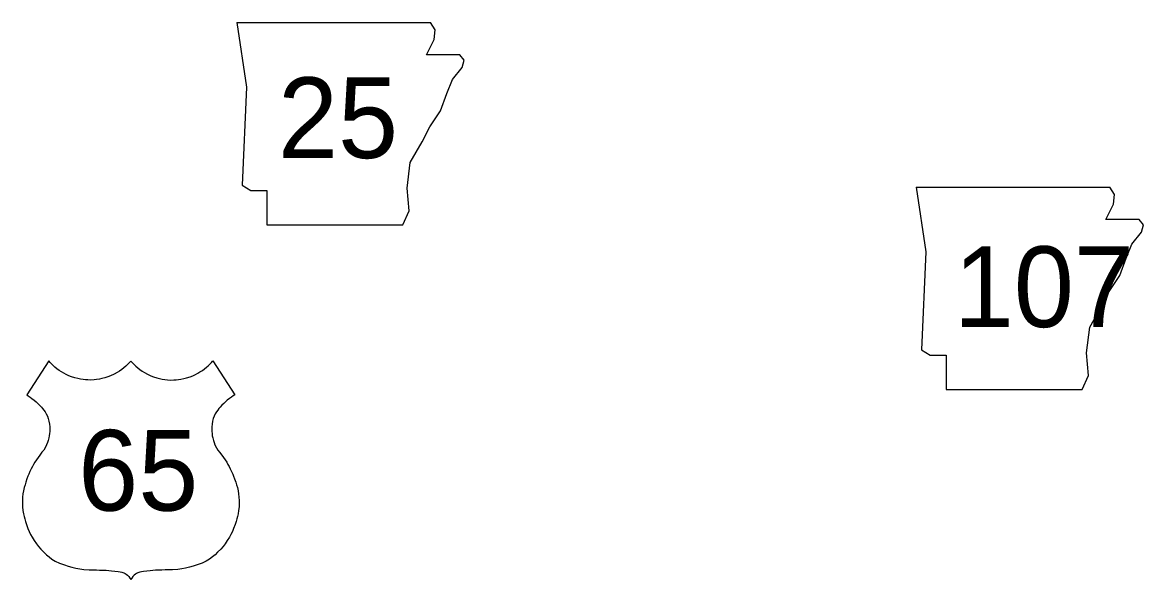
# Model space of a CAD drawing. Extents: x -819161 to 80911, y -6604 to 768454.
# Drawn here: x 43970 to 44849, y -2416 to -1978 of the extents above; entities that cross this region are included whole.
import ezdxf

# ---------------------------------------------------------------- set-up
doc = ezdxf.new("R2010")
doc.units = 0
doc.layers.add('Level 21', color=7, linetype='Continuous')
doc.layers.add('Level 22', color=7, linetype='Continuous')

msp = doc.modelspace()

# ---------------------------------------------------------------- linework, layer by layer
at = {"layer": 'Level 21'}
for p, q in [((44137.85, -1978.23), (44145.46, -2028.99)), ((44293.5, -1984.15), (44289.99, -1978.31)), ((44292.65, -1991.77), (44293.5, -1984.15)), ((44286.73, -2003.61), (44292.65, -1991.77)), ((44312.95, -2003.61), (44286.73, -2003.61)), ((44316.34, -2007.84), (44312.95, -2003.61)), ((44307.03, -2023.07), (44314.64, -2013.76)), ((44314.64, -2013.76), (44316.34, -2007.84)), ((44145.46, -2028.99), (44142.08, -2105.96)), ((44302.8, -2034.06), (44307.03, -2023.07)), ((44297.73, -2047.6), (44302.8, -2034.06)), ((44289.27, -2060.29), (44297.73, -2047.6)), ((44283.35, -2072.13), (44289.27, -2060.29)), ((44274.04, -2088.2), (44283.35, -2072.13)), ((44271.5, -2108.5), (44274.04, -2088.2)), ((44142.08, -2105.96), (44148.85, -2110.19)), ((44148.85, -2110.19), (44161.54, -2110.19)), ((44161.54, -2110.19), (44161.54, -2137.26)), ((44273.19, -2126.27), (44271.5, -2108.5)), ((44670.8, -2107.53), (44678.41, -2158.29)), ((44826.44, -2113.46), (44822.93, -2107.61)), ((44825.6, -2121.07), (44826.44, -2113.46)), ((44268.12, -2137.26), (44273.19, -2126.27)), ((44819.68, -2132.91), (44825.6, -2121.07)), ((44161.54, -2137.26), (44268.12, -2137.26)), ((44845.9, -2132.91), (44819.68, -2132.91)), ((44849.28, -2137.14), (44845.9, -2132.91)), ((44847.59, -2143.06), (44849.28, -2137.14)), ((44839.98, -2152.37), (44847.59, -2143.06)), ((44835.75, -2163.36), (44839.98, -2152.37)), ((44678.41, -2158.29), (44675.03, -2235.26)), ((44830.67, -2176.9), (44835.75, -2163.36)), ((44822.21, -2189.59), (44830.67, -2176.9)), ((44816.29, -2201.43), (44822.21, -2189.59)), ((44806.99, -2217.5), (44816.29, -2201.43)), ((44804.45, -2237.8), (44806.99, -2217.5)), ((44675.03, -2235.26), (44681.79, -2239.49)), ((44681.79, -2239.49), (44694.48, -2239.49)), ((44694.48, -2239.49), (44694.48, -2266.56)), ((44806.14, -2255.57), (44804.45, -2237.8)), ((44801.07, -2266.56), (44806.14, -2255.57)), ((44694.48, -2266.56), (44801.07, -2266.56))]:
    msp.add_line(p, q, dxfattribs=at)
for points in [[(44137.85, -1978.23), (44289.99, -1978.31)], [(44670.8, -2107.53), (44822.93, -2107.61)]]:
    msp.add_lwpolyline(points, dxfattribs=at)
at = {"layer": 'Level 22'}
for points in [[(44054.75, -2244.2), (44053.43, -2245.68), (44052.18, -2246.97), (44050.75, -2248.31), (44049.2, -2249.63), (44047.71, -2250.78), (44045.91, -2252.05), (44043.97, -2253.26), (44041.76, -2254.47), (44038.96, -2255.77), (44036.81, -2256.6), (44034.38, -2257.39), (44032.16, -2257.97), (44030.11, -2258.39), (44027.95, -2258.72), (44025.96, -2258.93), (44023.24, -2259.06), (44021.03, -2259.03), (44019.11, -2258.91), (44017.27, -2258.72), (44015.42, -2258.44), (44013.08, -2257.96), (44010.92, -2257.4), (44008.29, -2256.54), (44006.06, -2255.66), (44004.04, -2254.73), (44002.18, -2253.76), (44000.47, -2252.76), (43998.55, -2251.5), (43996.8, -2250.21), (43995.29, -2248.98), (43994.01, -2247.84), (43992.71, -2246.59), (43991.44, -2245.24), (43990.4, -2244.06), (43973.09, -2270.82), (43974.33, -2271.56), (43975.8, -2272.52), (43977.2, -2273.51), (43979.05, -2274.96), (43980.54, -2276.24), (43981.86, -2277.47), (43983.2, -2278.83), (43984.57, -2280.36), (43985.56, -2281.55), (43986.53, -2282.8), (43987.51, -2284.18), (43988.47, -2285.63), (43989.36, -2287.33), (43990.03, -2289.41), (43990.54, -2291.48), (43990.92, -2293.69), (43991.13, -2295.74), (43991.2, -2297.72), (43991.15, -2299.58), (43991.03, -2301.07), (43990.78, -2302.89), (43990.44, -2304.6), (43989.96, -2306.46), (43989.44, -2308.09), (43988.73, -2309.91), (43987.6, -2312.27), (43986.45, -2314.13), (43985.05, -2315.8), (43983.36, -2317.97), (43981.99, -2319.88), (43980.7, -2321.79), (43979.53, -2323.66), (43978.54, -2325.34), (43977.67, -2326.91), (43976.69, -2328.78), (43975.65, -2330.96), (43974.7, -2333.1), (43974.06, -2334.69), (43973.29, -2336.72), (43972.45, -2339.22), (43971.78, -2341.29), (43971.15, -2343.55), (43970.57, -2346.18), (43970.18, -2348.52), (43969.91, -2350.96), (43969.75, -2353.62), (43969.73, -2356.12), (43969.85, -2358.57), (43970.15, -2361.44), (43970.59, -2364.16), (43971.04, -2366.22), (43971.51, -2368.02), (43972.1, -2370.07), (43972.89, -2372.61), (43974.04, -2375.69), (43975.03, -2377.96), (43976.17, -2380.29), (43977.42, -2382.58), (43979.05, -2385.22), (43980.74, -2387.63), (43982.37, -2389.73), (43984.22, -2391.89), (43986.61, -2394.37), (43988.64, -2396.25), (43990.73, -2398)], [(44054.75, -2244.2), (44056.06, -2245.68), (44057.32, -2246.97), (44058.75, -2248.31), (44060.29, -2249.63), (44061.78, -2250.78), (44063.59, -2252.05), (44065.53, -2253.26), (44067.73, -2254.47), (44070.53, -2255.77), (44072.68, -2256.6), (44075.11, -2257.39), (44077.33, -2257.97), (44079.38, -2258.39), (44081.54, -2258.72), (44083.53, -2258.93), (44086.25, -2259.06), (44088.46, -2259.03), (44090.39, -2258.91), (44092.22, -2258.72), (44094.08, -2258.44), (44096.41, -2257.96), (44098.57, -2257.4), (44101.2, -2256.54), (44103.43, -2255.66), (44105.45, -2254.73), (44107.31, -2253.76), (44109.02, -2252.76), (44110.94, -2251.5), (44112.69, -2250.21), (44114.2, -2248.98), (44115.48, -2247.84), (44116.78, -2246.59), (44118.06, -2245.24), (44119.09, -2244.06), (44136.4, -2270.82), (44135.16, -2271.56), (44133.69, -2272.52), (44132.3, -2273.51), (44130.44, -2274.96), (44128.95, -2276.24), (44127.64, -2277.47), (44126.3, -2278.83), (44124.92, -2280.36), (44123.94, -2281.55), (44122.97, -2282.8), (44121.98, -2284.18), (44121.02, -2285.63), (44120.14, -2287.33), (44119.46, -2289.41), (44118.95, -2291.48), (44118.57, -2293.69), (44118.37, -2295.74), (44118.3, -2297.72), (44118.34, -2299.58), (44118.47, -2301.07), (44118.71, -2302.89), (44119.05, -2304.6), (44119.53, -2306.46), (44120.05, -2308.09), (44120.77, -2309.91), (44121.89, -2312.27), (44123.05, -2314.13), (44124.44, -2315.8), (44126.13, -2317.97), (44127.51, -2319.88), (44128.79, -2321.79), (44129.97, -2323.66), (44130.96, -2325.34), (44131.83, -2326.91), (44132.8, -2328.78), (44133.85, -2330.96), (44134.79, -2333.1), (44135.44, -2334.69), (44136.2, -2336.72), (44137.05, -2339.22), (44137.71, -2341.29), (44138.34, -2343.55), (44138.92, -2346.18), (44139.31, -2348.52), (44139.59, -2350.96), (44139.75, -2353.62), (44139.76, -2356.12), (44139.65, -2358.57), (44139.35, -2361.44), (44138.9, -2364.16), (44138.45, -2366.22), (44137.98, -2368.02), (44137.39, -2370.07), (44136.6, -2372.61), (44135.45, -2375.69), (44134.47, -2377.96), (44133.33, -2380.29), (44132.07, -2382.58), (44130.44, -2385.22), (44128.76, -2387.63), (44127.13, -2389.73), (44125.28, -2391.89), (44122.88, -2394.37), (44120.85, -2396.25), (44118.76, -2398)], [(43990.73, -2398), (43992.9, -2399.64), (43995.51, -2401.35), (43998.79, -2402.81), (44002.62, -2404.28), (44005.75, -2405.3), (44008.56, -2406.08), (44011.74, -2406.81), (44014.73, -2407.36), (44017.94, -2407.81), (44021.99, -2408.15), (44025.09, -2408.26), (44027.74, -2408.25), (44030.31, -2408.28), (44032.89, -2408.36), (44035.33, -2408.48), (44037.47, -2408.62), (44039.57, -2408.8), (44042.26, -2409.08), (44044.89, -2409.4), (44046.46, -2409.63), (44047.77, -2409.88), (44049.34, -2410.53), (44050.24, -2411.03), (44051.03, -2411.55), (44052.11, -2412.42), (44053.14, -2413.47), (44053.98, -2414.55), (44054.75, -2415.8)], [(44118.76, -2398), (44116.59, -2399.64), (44113.98, -2401.35), (44110.71, -2402.81), (44106.88, -2404.28), (44103.75, -2405.3), (44100.93, -2406.08), (44097.75, -2406.81), (44094.76, -2407.36), (44091.55, -2407.81), (44087.5, -2408.15), (44084.41, -2408.26), (44081.76, -2408.25), (44079.18, -2408.28), (44076.6, -2408.36), (44074.16, -2408.48), (44072.03, -2408.62), (44069.92, -2408.8), (44067.24, -2409.08), (44064.61, -2409.4), (44063.03, -2409.63), (44061.73, -2409.88), (44060.15, -2410.53), (44059.25, -2411.03), (44058.46, -2411.55), (44057.38, -2412.42), (44056.35, -2413.47), (44055.51, -2414.55), (44054.75, -2415.8)]]:
    msp.add_lwpolyline(points, dxfattribs=at)

# ---------------------------------------------------------------- texts
at = {"layer": 'Level 21'}
for s, p in [('25', (44170.21, -2084.78)), ('107', (44700.39, -2217.48))]:
    msp.add_text(s, height=63.36, dxfattribs=at).set_placement(p)
at = {"layer": 'Level 22'}
msp.add_text('65', height=63.36, dxfattribs=at).set_placement((44013.49, -2361.65))

doc.saveas('drawing.dxf')
